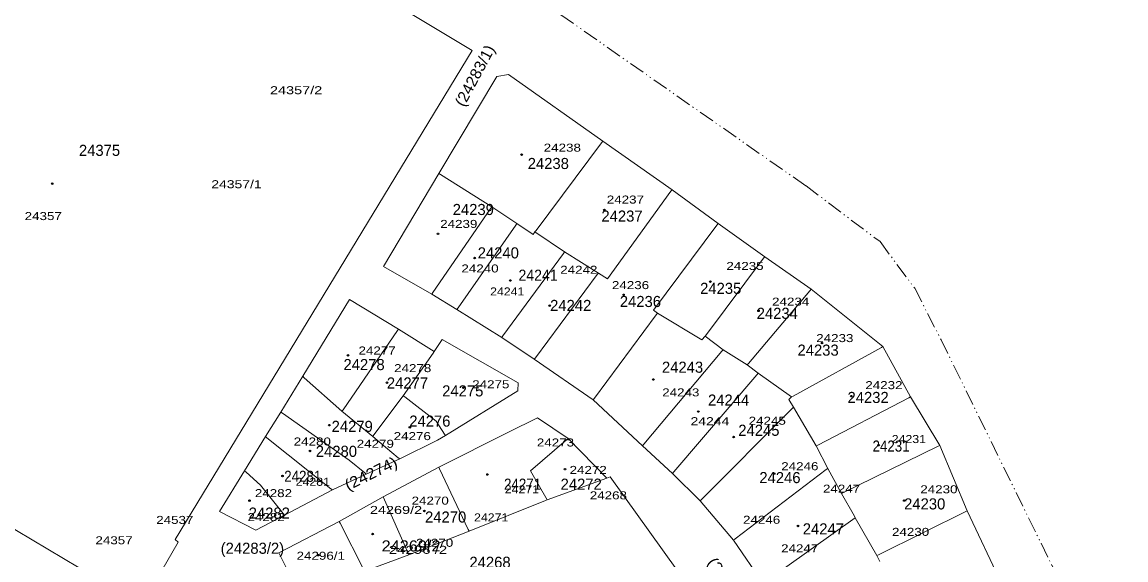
# Model space of a CAD drawing. Extents: x 649608 to 651081, y 237980 to 241202.
# Drawn here: x 650584.2 to 650942.7, y 238986.3 to 239160.9 of the extents above; entities that cross this region are included whole.
import ezdxf

# ---------------------------------------------------------------- set-up
doc = ezdxf.new("R2010")
doc.units = 0
doc.header["$PDMODE"] = 32
doc.header["$PDSIZE"] = 0.5
doc.linetypes.add('DASH_DOUBLE_DOT', pattern=[9.2, 5, -1.2, 0.3, -1.2, 0.3, -1.2])
for name, color, linetype in [('19', 7, 'Continuous'), ('20', 7, 'Continuous'), ('6', 7, 'Continuous')]:
    doc.layers.add(name, color=color, linetype=linetype)
for name, color, linetype, lineweight in [('3', 7, 'Continuous', 13), ('5', 7, 'Continuous', 13), ('52', 7, 'DASH_DOUBLE_DOT', 13)]:
    doc.layers.add(name, color=color, linetype=linetype, lineweight=lineweight)

msp = doc.modelspace()

# ---------------------------------------------------------------- linework, layer by layer
at = {"layer": '3'}
for p, q in [((650774.078, 239012.867), (650761.567, 239025.756)), ((650660.118, 238995.949), (650648.359, 239002.005)), ((650660.118, 238995.949), (650669.375, 239000.792))]:
    msp.add_line(p, q, dxfattribs=at)
for points in [[(650634.917, 238992.051), (650633.914, 238992.9), (650730.416, 239151.667), (650574.402, 239245.255), (650564.003, 239226.917), (650562.503, 239225.238), (650535.575, 239197.674), (650472.242, 239088.563), (650471.65, 239089.049), (650460.092, 239068.577)], [(650772.821, 239122.228), (650742.164, 239143.839), (650738.424, 239143.206), (650719.61, 239111.75)], [(650891.135, 239002.272), (650882.294, 239023.471), (650872.771, 239039.22), (650863.816, 239055.578), (650840.465, 239074.186), (650825.407, 239084.724), (650810.255, 239095.514), (650795.333, 239106.471), (650772.821, 239122.228)], [(650719.61, 239111.75), (650701.53, 239081.519), (650717.256, 239072.605), (650725.445, 239067.618), (650740.009, 239058.557), (650750.54, 239051.429), (650769.741, 239038.284), (650785.728, 239023.401), (650795.511, 239014.402), (650804.439, 239005.498)], [(650706.492, 239061.256), (650690.531, 239070.847), (650675.344, 239045.914), (650668.225, 239034.331), (650663.229, 239026.349), (650656.473, 239015.205), (650648.359, 239002.005)], [(650634.917, 238992.051), (650623.091, 238971.671), (650460.092, 239068.577)], [(650721.764, 239026.665), (650745.215, 239041.194), (650745.275, 239043.777), (650720.684, 239057.818), (650718.026, 239053.955), (650706.492, 239061.256)], [(650761.567, 239025.756), (650751.604, 239032.424), (650742.232, 239027.8), (650719.56, 239016.432), (650701.436, 239006.797)], [(650706.885, 239019.09), (650719.161, 239025.161), (650721.764, 239026.665)], [(650669.375, 239000.792), (650684.974, 239009.021), (650695.971, 239014.204), (650706.885, 239019.09)], [(650774.078, 239012.867), (650775.203, 239013.327), (650796.821, 238983.106), (650717.851, 238942.083), (650702.06, 238935.402), (650698.02, 238933.358), (650660.567, 238917.274), (650640.555, 238964.095), (650672.923, 238978.022), (650667.588, 238988.576)], [(650667.588, 238988.576), (650687.222, 238998.786), (650701.436, 239006.797)], [(650896.474, 238928.024), (650866.501, 238916.902), (650860.911, 238918.598), (650838.751, 238956.69), (650832.15, 238968.489), (650824.903, 238978.716), (650815.286, 238992.747), (650804.439, 239005.498)], [(650919.551, 238936.638), (650914.867, 238948.335), (650906.317, 238969.569), (650902.354, 238978.677), (650891.135, 239002.272)]]:
    msp.add_lwpolyline(points, dxfattribs=at)
at = {"layer": '5'}
msp.add_line((650789.255, 239067.413), (650790.565, 239066.389), dxfattribs=at)
for points in [[(650750.782, 239092.785), (650751.156, 239093.285), (650772.447, 239121.728), (650772.821, 239122.228)], [(650719.61, 239111.75), (650720.11, 239111.435), (650736.752, 239100.964), (650744.905, 239095.506)], [(650771.412, 239079.433), (650774.339, 239077.576), (650794.97, 239105.971), (650795.333, 239106.471)], [(650736.752, 239100.964), (650736.408, 239100.464), (650717.6, 239073.105), (650717.256, 239072.605)], [(650744.905, 239095.506), (650744.556, 239095.006), (650725.794, 239068.118), (650725.445, 239067.618)], [(650744.905, 239095.506), (650750.147, 239091.951), (650750.782, 239092.785), (650760.423, 239086.323), (650771.412, 239079.433)], [(650789.255, 239067.413), (650809.881, 239095.014), (650810.255, 239095.514)], [(650760.423, 239086.323), (650760.055, 239085.823), (650740.377, 239059.057), (650740.009, 239058.557)], [(650806.123, 239058.944), (650806.497, 239059.444), (650825.033, 239084.224), (650825.407, 239084.724)], [(650771.412, 239079.433), (650771.039, 239078.933), (650750.913, 239051.929), (650750.54, 239051.429)], [(650819.699, 239049.607), (650820.121, 239050.107), (650840.043, 239073.686), (650840.465, 239074.186)], [(650790.565, 239066.389), (650790.195, 239065.889), (650770.111, 239038.784), (650769.741, 239038.284)], [(650790.565, 239066.389), (650804.989, 239057.803), (650806.123, 239058.944), (650811.936, 239054.559), (650819.699, 239049.607), (650823.235, 239046.916), (650834.106, 239039.233)], [(650688.093, 239034.585), (650688.438, 239035.085), (650706.147, 239060.756), (650706.492, 239061.256)], [(650834.106, 239039.233), (650834.606, 239039.508), (650863.316, 239055.303), (650863.816, 239055.578)], [(650707.972, 239039.634), (650717.675, 239053.455), (650718.026, 239053.955)], [(650811.936, 239054.559), (650811.515, 239054.059), (650786.149, 239023.901), (650785.728, 239023.401)], [(650675.344, 239045.914), (650675.844, 239045.47), (650688.093, 239034.585), (650698.07, 239026.401)], [(650823.235, 239046.916), (650822.809, 239046.416), (650795.937, 239014.902), (650795.511, 239014.402)], [(650698.07, 239026.401), (650698.444, 239026.901), (650707.972, 239039.634)], [(650707.972, 239039.634), (650708.472, 239039.25), (650718.679, 239031.408), (650721.439, 239027.165), (650721.764, 239026.665)], [(650834.106, 239039.233), (650833.206, 239038.434), (650834.732, 239035.914), (650842.165, 239023.344), (650845.92, 239016.002), (650850.387, 239007.923)], [(650842.165, 239023.344), (650842.665, 239023.603), (650872.271, 239038.961), (650872.771, 239039.22)], [(650668.225, 239034.331), (650668.725, 239033.98), (650690.464, 239018.73), (650695.471, 239014.615), (650695.971, 239014.204)], [(650834.732, 239035.914), (650834.234, 239035.414), (650804.439, 239005.498)], [(650663.229, 239026.349), (650663.729, 239025.951), (650684.474, 239009.419), (650684.974, 239009.021)], [(650698.07, 239026.401), (650706.385, 239019.505), (650706.885, 239019.09)], [(650761.567, 239025.756), (650761.067, 239025.329), (650749.313, 239015.287), (650754.754, 239005.769), (650774.078, 239012.867)], [(650850.387, 239007.923), (650881.794, 239023.227), (650882.294, 239023.471)], [(650719.56, 239016.432), (650719.796, 239015.932), (650729.133, 238996.182), (650729.369, 238995.682)], [(650815.286, 238992.747), (650815.786, 238993.127), (650845.42, 239015.622), (650845.92, 239016.002)], [(650656.473, 239015.205), (650656.973, 239014.752), (650661.624, 239010.538), (650669.375, 239000.792)], [(650709.782, 238988.02), (650709.56, 238988.52), (650701.436, 239006.797)], [(650729.369, 238995.682), (650754.254, 239005.57), (650754.754, 239005.769)], [(650850.387, 239007.923), (650854.529, 239000.528), (650854.809, 239000.028)], [(650861.825, 238987.705), (650862.325, 238987.953), (650891.135, 239002.272)], [(650687.222, 238998.786), (650687.478, 238998.286), (650695.228, 238983.119), (650695.484, 238982.619)], [(650824.903, 238978.716), (650825.403, 238979.072), (650854.809, 239000.028), (650861.825, 238987.705), (650862.766, 238985.824)], [(650672.923, 238978.022), (650673.423, 238978.231), (650678.034, 238980.155), (650679.962, 238976.95), (650695.484, 238982.619), (650709.782, 238988.02), (650729.369, 238995.682)]]:
    msp.add_lwpolyline(points, dxfattribs=at)
at = {"layer": '52'}
msp.add_lwpolyline([(650586.911, 239277.281), (650736.548, 239179.048), (650838.83, 239107.702), (650862.891, 239089.627), (650874.137, 239074.489), (650882.719, 239057.758), (650918.743, 238984.453), (650942.749, 238932.427)], dxfattribs=at)
at = {"layer": '6'}
for p in [(650746.432, 239117.895), (650593.974, 239108.463), (650773.335, 239099.902), (650719.308, 239092.177), (650731.185, 239084.291), (650742.802, 239077.031), (650807.769, 239076.658), (650779.559, 239072.377), (650755.57, 239068.876), (650823.403, 239067.165), (650844.048, 239056.709), (650690.044, 239052.716), (650789.223, 239044.895), (650702.693, 239043.828), (650727.521, 239042.241), (650853.58, 239039.461), (650803.839, 239034.48), (650683.963, 239030.059), (650710.148, 239029.362), (650815.321, 239026.207), (650862.418, 239023.571), (650677.679, 239021.676), (650760.568, 239015.762), (650668.771, 239013.57), (650735.351, 239014.053), (650828.477, 239014.33), (650658.062, 239005.577), (650870.723, 239005.588), (650714.872, 239002.226), (650836.212, 238997.359), (650698.058, 238994.708), (650680.374, 238987.868)]:
    msp.add_point(p, dxfattribs=at)

# ---------------------------------------------------------------- texts
at = {"layer": '19'}
for s, rotation, width, p in [('(24283/1)', 61.874, 1.05, (650727.739, 239133.134)), ('(24274)', 26.167, 1.1, (650690.107, 239008.725)), ('(24251)', 307.246, 1.1, (650806.548, 238985.389))]:
    msp.add_text(s, height=3.6, rotation=rotation, dxfattribs=dict(at, width=width)).set_placement(p)
for s, p in [('24375', (650602.644, 239117.463)), ('24238', (650748.425, 239113.198)), ('24239', (650724.058, 239098.267)), ('24237', (650772.367, 239096.133)), ('24240', (650732.181, 239084.188)), ('24235', (650804.429, 239072.67)), ('24242', (650755.694, 239067.124)), ('24236', (650778.352, 239068.404)), ('24234', (650822.812, 239064.564)), ('24233', (650836.065, 239052.619)), ('24278', (650688.573, 239047.927)), ('24243', (650792.032, 239047.073)), ('24277', (650702.682, 239041.954)), ('24275', (650720.637, 239039.394)), ('24232', (650852.31, 239037.261)), ('24244', (650806.995, 239036.408)), ('24279', (650684.727, 239027.876)), ('24276', (650709.95, 239029.582)), ('24245', (650816.828, 239026.596)), ('24280', (650679.596, 239019.77)), ('24272', (650759.112, 239009.105)), ('24246', (650823.668, 239011.238)), ('24230', (650870.693, 239002.706)), ('24282', (650657.792, 238999.72)), ('24270', (650715.078, 238998.44)), ('24247', (650837.776, 238994.6)), ('(24283/2)', (650648.694, 238988.3)), ('24268', (650729.493, 238983.745))]:
    msp.add_text(s, height=3.6, dxfattribs=at).set_placement(p)
for s, width, p in [('24241', 0.95, (650745.434, 239076.936)), ('24231', 0.9, (650860.433, 239021.477)), ('24281', 0.9, (650669.335, 239011.665)), ('24271', 0.9, (650740.729, 239009.105)), ('24269/2', 1.1, (650700.971, 238989.054))]:
    msp.add_text(s, height=3.6, dxfattribs=dict(at, width=width)).set_placement(p)
at = {"layer": '20'}
for s, width, p in [('24357/2', 1.35, (650664.717, 239137.482)), ('24238', 1.25, (650753.623, 239118.839)), ('24357/1', 1.3, (650645.657, 239106.971)), ('24237', 1.25, (650774.116, 239101.989)), ('24357', 1.25, (650585.017, 239096.629)), ('24239', 1.25, (650719.999, 239094.083)), ('24240', 1.25, (650726.889, 239079.624)), ('24242', 1.25, (650758.984, 239079.196)), ('24235', 1.25, (650812.969, 239080.44)), ('24236', 1.25, (650775.787, 239074.216)), ('24241', 1.15, (650736.219, 239072.161)), ('24234', 1.25, (650827.804, 239068.859)), ('24233', 1.25, (650842.142, 239057.02)), ('24277', 1.25, (650693.466, 239052.994)), ('24278', 1.25, (650705.026, 239047.274)), ('24275', 1.25, (650730.401, 239042.028)), ('24232', 1.25, (650858.095, 239041.749)), ('24243', 1.25, (650792.116, 239039.401)), ('24244', 1.3, (650801.339, 239030.05)), ('24245', 1.25, (650820.203, 239030.19)), ('24276', 1.25, (650704.891, 239025.209)), ('24231', 1.15, (650866.689, 239024.248)), ('24280', 1.25, (650672.412, 239023.456)), ('24279', 1.25, (650692.884, 239022.72)), ('24273', 1.25, (650751.389, 239023.135)), ('24272', 1.25, (650762.031, 239014.227)), ('24246', 1.25, (650830.782, 239015.434)), ('24281', 1.15, (650673.065, 239010.38)), ('24282', 1.25, (650659.791, 239006.703)), ('24271', 1.15, (650740.979, 239007.934)), ('24268', 1.25, (650768.587, 239005.973)), ('24247', 1.25, (650844.336, 239008.142)), ('24230', 1.25, (650875.952, 239007.949)), ('24270', 1.25, (650710.708, 239004.265)), ('24282', 1.25, (650657.41, 238998.926)), ('24269/2', 1.35, (650697.165, 239001.241)), ('24271', 1.15, (650731.007, 238998.822)), ('24537', 1.25, (650627.754, 238998.001)), ('24246', 1.25, (650818.375, 238998.058)), ('24357', 1.25, (650608.006, 238991.394)), ('24230', 1.25, (650866.763, 238994.128)), ('24296 /2', 1.4, (650703.319, 238988.29)), ('24270', 1.25, (650712.147, 238990.573)), ('24247', 1.25, (650830.735, 238988.778)), ('24296/1', 1.25, (650673.349, 238986.373))]:
    msp.add_text(s, height=2.6, dxfattribs=dict(at, width=width)).set_placement(p)

doc.saveas('drawing.dxf')
